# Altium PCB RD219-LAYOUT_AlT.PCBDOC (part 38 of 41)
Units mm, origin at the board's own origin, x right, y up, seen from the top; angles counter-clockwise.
Board outline 209.75 x 159.97 mm, 2 copper layers (TOP, BOTTOM), stack 0 mm thick; 398 components, 199 nets, 1469 pads, 0 vias.
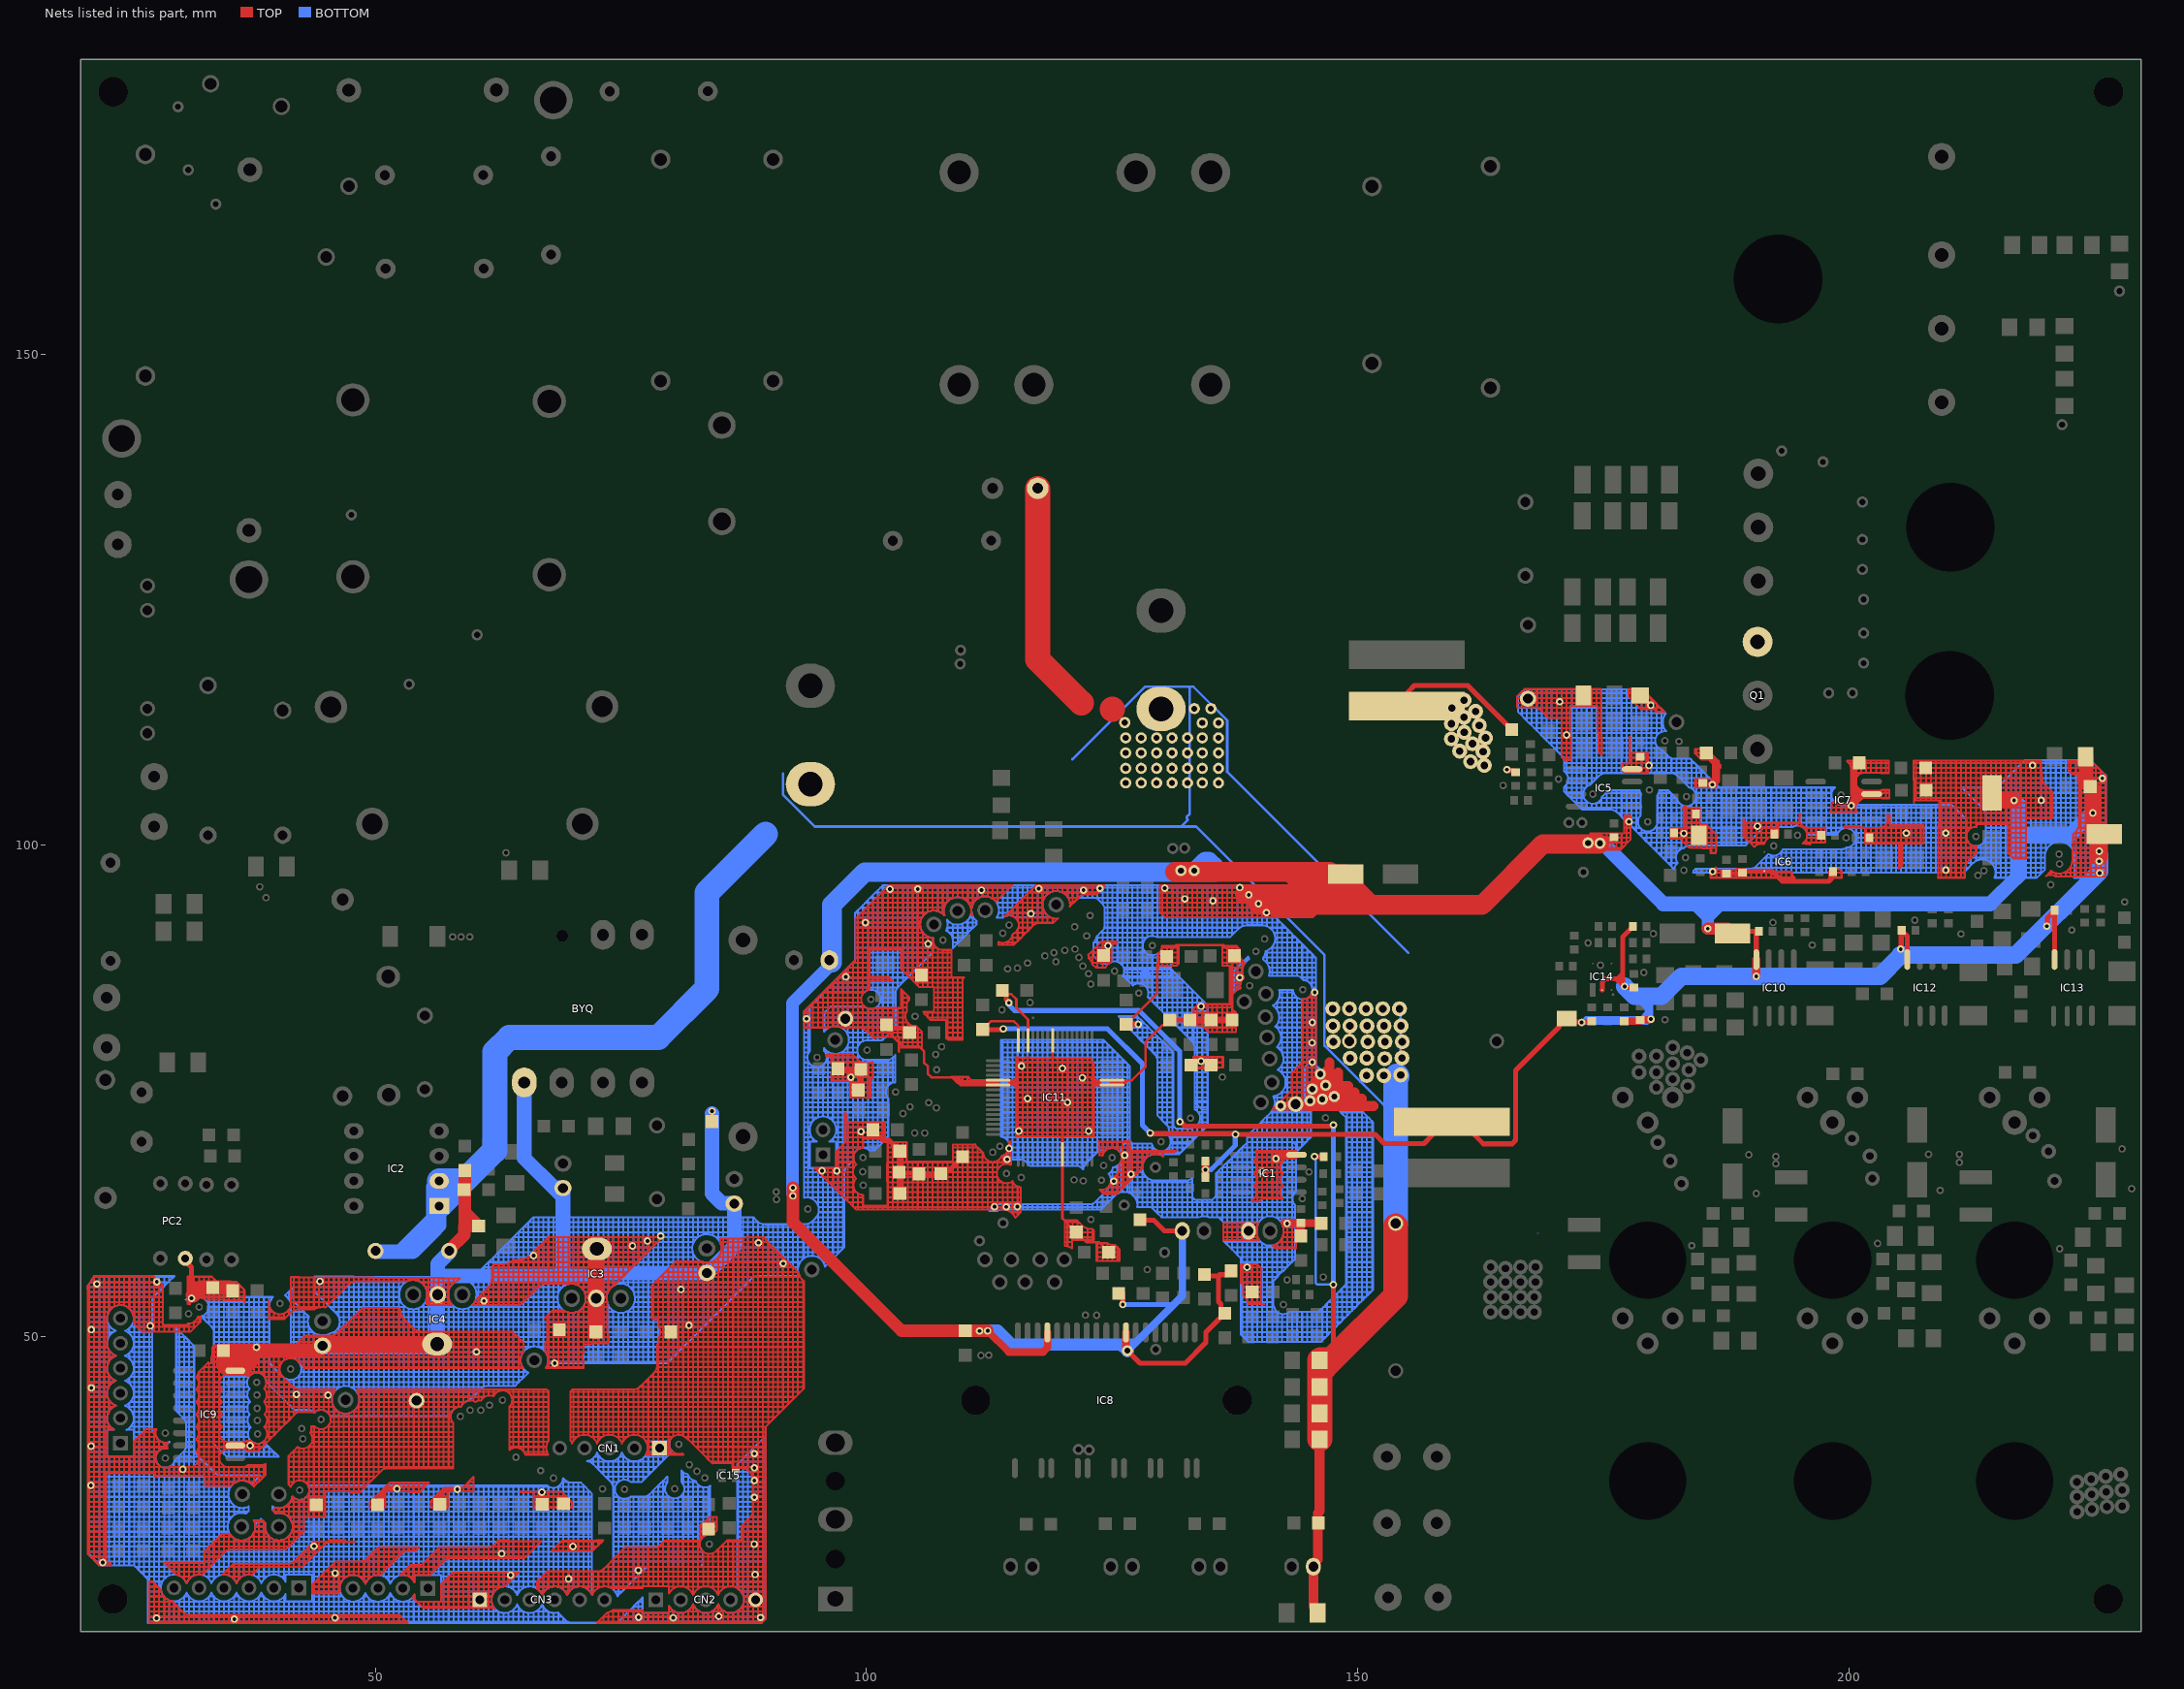
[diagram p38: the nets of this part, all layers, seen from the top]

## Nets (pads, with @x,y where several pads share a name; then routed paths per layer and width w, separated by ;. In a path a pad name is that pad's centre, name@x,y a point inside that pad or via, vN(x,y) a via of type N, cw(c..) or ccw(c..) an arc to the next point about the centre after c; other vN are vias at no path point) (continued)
GND: (continued)
  BOTTOM w0.203: 210.373,102.296 210.881,102.296 ; 210.373,102.804 210.373,103.312 ; 210.373,102.804 210.881,102.804 ; 210.373,103.312 210.373,103.82 ; 210.373,103.312 210.881,103.312 ; 210.373,103.82 210.373,104.107 ; 210.373,103.82 210.761,103.82 ; 210.373,104.107 210.474,104.107 210.761,103.82 ; 210.761,103.82 210.881,103.7 ; 210.881,97.212 210.881,97.216 ; 210.881,97.212 211.389,97.212 ; 210.881,97.216 210.881,97.724 ; 210.881,97.216 211.389,97.216 ; 210.881,97.724 210.881,98.232 ; 210.881,97.724 211.389,97.724 ; 210.881,98.232 210.881,98.74 ; 210.881,98.232 211.389,98.232 ; 210.881,98.74 210.881,99.248 ; 210.881,98.74 211.389,98.74 ; 210.881,99.248 210.881,99.756 ; 210.881,99.248 211.389,99.248 ; 210.881,99.756 210.881,100.264 ; 210.881,99.756 211.389,99.756 ; 210.881,100.264 210.881,100.772 ; 210.881,100.264 211.389,100.264 ; 210.881,100.772 210.881,101.28 ; 210.881,100.772 211.389,100.772 ; 210.881,101.28 210.881,101.788 ; 210.881,101.28 211.389,101.28 ; 210.881,101.788 210.881,102.296 ; 210.881,101.788 211.389,101.788 ; 210.881,102.296 210.881,102.804 ; 210.881,102.296 211.389,102.296 ; 210.881,102.804 210.881,103.312 ; 210.881,102.804 211.389,102.804 ; 210.881,103.312 210.881,103.7 ; 210.881,103.312 211.269,103.312 ; 210.881,103.7 211.269,103.312 ; 211.269,103.312 211.389,103.192 ; 211.389,97.212 211.389,97.216 ; 211.389,97.212 211.632,97.212 211.637,97.216 ; 211.389,97.216 211.389,97.724 ; 211.389,97.216 211.637,97.216 ; 211.389,97.724 211.897,97.724 ; 211.389,97.724 211.389,98.232 ; 211.389,98.232 211.897,98.232 ; 211.389,98.232 211.389,98.74 ; 211.389,98.74 211.897,98.74 ; 211.389,98.74 211.389,99.248 ; 211.389,99.248 211.389,99.756 ; 211.389,99.248 211.897,99.248 ; 211.389,99.756 211.897,99.756 ; 211.389,99.756 211.389,100.264 ; 211.389,100.264 211.389,100.772 ; 211.389,100.264 211.897,100.264 ; 211.389,100.772 211.897,100.772 ; 211.389,100.772 211.389,101.28 ; 211.389,101.28 211.389,101.788 ; 211.389,101.28 211.897,101.28 ; 211.389,101.788 211.389,102.296 ; 211.389,101.788 211.897,101.788 ; 211.389,102.296 211.897,102.296 ; 211.389,102.296 211.389,102.804 ; 211.389,102.804 211.389,103.192 ; 211.389,102.804 211.777,102.804 ; 211.389,103.192 211.777,102.804 ; 211.501,105.852 cw(c210.881,105.09) 211.576,105.785 ccw(c210.881,105.09) 211.501,105.852 ; 211.501,105.852 ccw(c210.881,105.09) 211.459,105.885 cw(c210.881,105.09) 211.501,105.852 ; 211.501,105.852 211.897,105.852 ; 211.637,97.216 211.897,97.476 ; 211.777,102.804 211.897,102.684 ; 211.897,97.476 212.145,97.724 ; 211.897,97.476 211.897,97.724 ; 211.897,97.724 211.897,98.232 ; 211.897,97.724 212.145,97.724 ; 211.897,98.232 211.897,98.74 ; 211.897,98.232 212.405,98.232 ; 211.897,98.74 211.897,99.248 ; 211.897,98.74 212.405,98.74 ; 211.897,99.248 211.897,99.756 ; 211.897,99.248 212.405,99.248 ; 211.897,99.756 212.405,99.756 ; 211.897,99.756 211.897,100.264 ; 211.897,100.264 211.897,100.772 ; 211.897,100.264 212.168,100.264 ; 211.897,100.772 211.897,101.28 ; 211.897,100.772 211.939,100.772 ; 211.897,101.28 211.897,101.788 ; 211.897,101.28 211.93,101.28 ; 211.897,101.788 211.897,102.296 ; 211.897,101.788 211.93,101.788 ; 211.897,102.296 211.93,102.296 ; 211.897,102.296 211.897,102.684 ; 211.897,102.684 211.93,102.651 211.93,102.296 ; 211.897,105.464 212.017,105.344 ; 211.897,105.464 211.897,105.852 ; 211.897,105.852 211.897,105.886 ; 211.897,105.852 212.405,105.852 ; 211.897,105.886 212.405,105.886 ; 211.93,100.905 ccw(c212.913,100.905) 211.939,100.772 ; 211.93,100.905 ccw(c212.913,100.905) 211.939,100.772 ; 211.93,100.905 211.93,101.28 ; 211.93,101.28 211.93,101.788 ; 211.93,101.788 211.93,102.296 ; 211.939,100.772 ccw(c212.913,100.905) 212.168,100.264 ; 211.939,100.772 ccw(c212.913,100.905) 212.168,100.264 ; 212.017,105.344 212.405,104.956 ; 212.017,105.344 212.405,105.344 ; 212.145,97.724 212.405,97.984 ; 212.168,100.264 ccw(c212.913,100.905) 212.171,100.26 ; 212.168,100.264 ccw(c212.913,100.905) 212.171,100.26 ; 212.171,100.26 ccw(c212.913,100.905) 212.405,100.064 ; 212.171,100.26 ccw(c212.913,100.905) 212.405,100.064 ; 212.405,97.984 212.592,98.172 cw(c213.548,97.216) 212.657,98.232 ; 212.405,97.984 212.405,98.232 ; 212.405,98.232 212.405,98.74 ; 212.405,98.232 212.657,98.232 ; 212.405,98.74 212.405,99.248 ; 212.405,98.74 212.913,98.74 ; 212.405,99.248 212.405,99.756 ; 212.405,99.248 212.913,99.248 ; 212.405,99.756 212.913,99.756 ; 212.405,99.756 212.405,100.064 ; 212.405,100.064 ccw(c212.913,100.905) 212.407,100.063 ; 212.405,100.064 ccw(c212.913,100.905) 212.407,100.063 ; 212.405,104.956 212.525,104.836 ; 212.405,104.956 212.405,105.344 ; 212.405,105.344 212.405,105.852 ; 212.405,105.344 212.913,105.344 ; 212.405,105.852 212.405,105.886 ; 212.405,105.852 212.913,105.852 ; 212.405,105.886 212.913,105.886 ; 212.407,100.063 ccw(c212.913,100.905) 212.913,99.923 ; 212.407,100.063 ccw(c212.913,100.905) 212.913,99.923 ; 212.525,104.836 212.913,104.448 ; 212.525,104.836 212.913,104.836 ; 212.657,98.232 cw(c213.548,97.216) 212.913,98.409 ; 212.913,98.409 cw(c213.548,97.216) 213.421,98.562 ; 212.913,98.409 212.913,98.74 ; 212.913,98.74 212.913,99.248 ; 212.913,98.74 213.421,98.74 ; 212.913,99.248 212.913,99.756 ; 212.913,99.248 213.421,99.248 ; 212.913,99.756 213.421,99.756 ; 212.913,99.756 212.913,99.923 ; 212.913,99.923 ccw(c212.913,100.905) 213.419,100.063 ; 212.913,99.923 ccw(c212.913,100.905) 213.419,100.063 ; 212.913,104.448 213.033,104.328 ; 212.913,104.448 212.913,104.836 ; 212.913,104.836 212.913,105.344 ; 212.913,104.836 213.421,104.836 ; 212.913,105.344 212.913,105.852 ; 212.913,105.344 213.421,105.344 ; 212.913,105.852 213.421,105.852 ; 212.913,105.852 212.913,105.886 ; 212.913,105.886 213.421,105.886 ; 213.033,104.328 213.421,104.328 ; 213.419,100.063 ccw(c212.913,100.905) 213.421,100.064 ; 213.419,100.063 ccw(c212.913,100.905) 213.421,100.064 ; 213.421,98.562 cw(c213.548,97.216) 213.921,98.515 cw(c213.548,97.216) 213.929,98.513 ; 213.421,98.562 213.421,98.74 ; 213.421,98.74 213.421,99.248 ; 213.421,98.74 213.929,98.74 ; 213.421,99.248 213.421,99.756 ; 213.421,99.248 213.929,99.248 ; 213.421,99.756 213.929,99.756 ; 213.421,99.756 213.421,100.064 ; 213.421,100.064 ccw(c212.913,100.905) 213.654,100.26 ; 213.421,100.064 ccw(c212.913,100.905) 213.654,100.26 ; 213.421,104.328 213.421,104.836 ; 213.421,104.328 213.929,104.328 ; 213.421,104.836 213.421,105.344 ; 213.421,104.836 213.929,104.836 ; 213.421,105.344 213.421,105.852 ; 213.421,105.344 213.929,105.344 ; 213.421,105.852 213.929,105.852 ; 213.421,105.852 213.421,105.886 ; 213.421,105.886 213.929,105.886 ; 213.654,100.26 ccw(c212.913,100.905) 213.657,100.264 ; 213.654,100.26 ccw(c212.913,100.905) 213.657,100.264 ; 213.657,100.264 ccw(c212.913,100.905) 213.886,100.772 ; 213.657,100.264 ccw(c212.913,100.905) 213.886,100.772 ; 213.657,100.264 213.929,100.264 ; 213.862,103.312 ccw(c212.913,103.058) 213.608,103.753 cw(c212.913,103.058) 213.862,103.312 ; 213.862,103.312 cw(c212.913,103.058) 213.895,103.058 ; 213.862,103.312 cw(c212.913,103.058) 213.895,103.058 ; 213.862,103.312 213.929,103.312 ; 213.886,100.772 ccw(c212.913,100.905) 213.895,100.905 ; 213.886,100.772 ccw(c212.913,100.905) 213.895,100.905 ; 213.886,100.772 213.929,100.772 ; 213.895,100.905 213.895,101.28 ; 213.895,101.28 213.929,101.28 ; 213.895,101.28 213.895,101.788 ; 213.895,101.788 213.929,101.788 ; 213.895,101.788 213.895,102.296 ; 213.895,102.296 213.929,102.296 ; 213.895,102.296 213.895,102.804 ; 213.895,102.804 213.929,102.804 ; 213.895,102.804 213.895,103.058 ; 213.929,98.513 cw(c213.548,97.216) 214.435,98.236 cw(c213.548,97.216) 214.437,98.234 ; 213.929,98.513 213.929,98.74 ; 213.929,98.74 213.929,99.248 ; 213.929,98.74 214.437,98.74 ; 213.929,99.248 213.929,99.756 ; 213.929,99.248 214.437,99.248 ; 213.929,99.756 213.929,100.264 ; 213.929,99.756 214.437,99.756 ; 213.929,100.264 213.929,100.772 ; 213.929,100.264 214.437,100.264 ; 213.929,100.772 214.437,100.772 ; 213.929,100.772 213.929,101.28 ; 213.929,101.28 213.929,101.788 ; 213.929,101.28 214.437,101.28 ; 213.929,101.788 213.929,102.296 ; 213.929,101.788 214.437,101.788 ; 213.929,102.296 213.929,102.804 ; 213.929,102.296 214.437,102.296 ; 213.929,102.804 213.929,103.312 ; 213.929,102.804 214.437,102.804 ; 213.929,103.312 213.929,103.82 ; 213.929,103.312 214.437,103.312 ; 213.929,103.82 213.929,104.328 ; 213.929,103.82 214.437,103.82 ; 213.929,104.328 213.929,104.836 ; 213.929,104.328 214.437,104.328 ; 213.929,104.836 213.929,105.344 ; 213.929,104.836 214.437,104.836 ; 213.929,105.344 213.929,105.852 ; 213.929,105.344 214.437,105.344 ; 213.929,105.852 213.929,105.886 ; 213.929,105.852 214.437,105.852 ; 213.929,105.886 214.437,105.886 ; 214.437,98.234 cw(c213.548,97.216) 214.439,98.232 ; 214.437,98.234 214.437,98.74 ; 214.437,98.74 214.945,98.74 ; 214.437,98.74 214.437,99.248 ; 214.437,99.248 214.437,99.756 ; 214.437,99.248 214.945,99.248 ; 214.437,99.756 214.945,99.756 ; 214.437,99.756 214.437,100.264 ; 214.437,100.264 214.437,100.772 ; 214.437,100.264 214.945,100.264 ; 214.437,100.772 214.945,100.772 ; 214.437,100.772 214.437,101.28 ; 214.437,101.28 214.437,101.788 ; 214.437,101.28 214.945,101.28 ; 214.437,101.788 214.437,102.296 ; 214.437,101.788 214.945,101.788 ; 214.437,102.296 214.437,102.804 ; 214.437,102.296 214.945,102.296 ; 214.437,102.804 214.437,103.312 ; 214.437,102.804 214.945,102.804 ; 214.437,103.312 214.437,103.82 ; 214.437,103.312 214.945,103.312 ; 214.437,103.82 214.945,103.82 ; 214.437,103.82 214.437,104.328 ; 214.437,104.328 214.437,104.836 ; 214.437,104.328 214.945,104.328 ; 214.437,104.836 214.437,105.344 ; 214.437,104.836 214.945,104.836 ; 214.437,105.344 214.437,105.852 ; 214.437,105.344 214.945,105.344 ; 214.437,105.852 214.945,105.852 ; 214.437,105.852 214.437,105.886 ; 214.437,105.886 214.731,105.886 ; 214.439,98.232 cw(c213.548,97.216) 214.801,97.724 ; 214.439,98.232 214.945,98.232 ; 214.731,105.886 ccw(c214.731,106.742) 214.945,105.913 ; 214.731,105.886 ccw(c214.731,106.742) 214.945,105.913 ; 214.801,97.724 cw(c213.548,97.216) 214.801,97.722 cw(c213.548,97.216) 214.9,97.216 ; 214.801,97.724 214.945,97.724 ; 214.9,97.216 214.945,97.216 ; 214.945,96.708 214.945,97.216 ; 214.945,96.708 215.453,96.708 ; 214.945,96.708 214.801,96.708 214.945,96.708 ; 214.945,96.708 215.453,96.708 ; 214.945,97.216 215.453,97.216 ; 214.945,97.216 214.945,97.724 ; 214.945,97.724 214.945,98.232 ; 214.945,97.724 215.453,97.724 ; 214.945,98.232 214.945,98.74 ; 214.945,98.232 215.453,98.232 ; 214.945,98.74 215.453,98.74 ; 214.945,98.74 214.945,99.248 ; 214.945,99.248 214.945,99.756 ; 214.945,99.248 215.453,99.248 ; 214.945,99.756 215.453,99.756 ; 214.945,99.756 214.945,100.264 ; 214.945,100.264 214.945,100.772 ; 214.945,100.264 215.453,100.264 ; 214.945,100.772 215.453,100.772 ; 214.945,100.772 214.945,101.28 ; 214.945,101.28 214.945,101.788 ; 214.945,101.28 215.453,101.28 ; 214.945,101.788 214.945,102.296 ; 214.945,101.788 215.453,101.788 ; 214.945,102.296 214.945,102.804 ; 214.945,102.296 215.453,102.296 ; 214.945,102.804 214.945,103.312 ; 214.945,102.804 215.453,102.804 ; 214.945,103.312 214.945,103.82 ; 214.945,103.312 215.453,103.312 ; 214.945,103.82 214.945,104.328 ; 214.945,103.82 215.453,103.82 ; 214.945,104.328 214.945,104.836 ; 214.945,104.328 215.453,104.328 ; 214.945,104.836 214.945,105.344 ; 214.945,104.836 215.453,104.836 ; 214.945,105.344 214.945,105.852 ; 214.945,105.344 215.453,105.344 ; 214.945,105.852 215.453,105.852 ; 214.945,105.852 214.945,105.913 ; 214.945,105.913 ccw(c214.731,106.742) 215.336,106.137 ; 214.945,105.913 ccw(c214.731,106.742) 215.336,106.137 ; 215.336,106.137 215.453,106.254 ; 215.453,96.708 215.453,97.216 ; 215.453,96.708 215.961,96.708 ; 215.453,96.708 215.961,96.708 ; 215.453,97.216 215.961,97.216 ; 215.453,97.216 215.453,97.724 ; 215.453,97.724 215.453,98.232 ; 215.453,97.724 215.961,97.724 ; 215.453,98.232 215.453,98.74 ; 215.453,98.232 215.961,98.232 ; 215.453,98.74 215.453,99.248 ; 215.453,98.74 215.961,98.74 ; 215.453,99.248 215.453,99.756 ; 215.453,99.248 215.961,99.248 ; 215.453,99.756 215.961,99.756 ; 215.453,99.756 215.453,100.264 ; 215.453,100.264 215.453,100.772 ; 215.453,100.264 215.961,100.264 ; 215.453,100.772 215.453,101.28 ; 215.453,100.772 215.961,100.772 ; 215.453,101.28 215.453,101.788 ; 215.453,101.28 215.961,101.28 ; 215.453,101.788 215.453,102.296 ; 215.453,101.788 215.961,101.788 ; 215.453,102.296 215.453,102.804 ; 215.453,102.296 215.961,102.296 ; 215.453,102.804 215.453,103.312 ; 215.453,102.804 215.961,102.804 ; 215.453,103.312 215.453,103.82 ; 215.453,103.312 215.961,103.312 ; 215.453,103.82 215.453,104.328 ; 215.453,103.82 215.961,103.82 ; 215.453,104.328 215.453,104.836 ; 215.453,104.328 215.961,104.328 ; 215.453,104.836 215.453,105.344 ; 215.453,104.836 215.961,104.836 ; 215.453,105.344 215.453,105.852 ; 215.453,105.344 215.961,105.344 ; 215.453,105.852 215.961,105.852 ; 215.453,105.852 215.453,106.254 ; 215.453,106.254 215.559,106.36 ; 215.559,106.36 215.961,106.762 ; 215.559,106.36 215.961,106.36 ; 215.961,96.708 215.961,97.216 ; 215.961,96.708 216.469,96.708 ; 215.961,96.708 216.469,96.708 ; 215.961,97.216 216.469,97.216 ; 215.961,97.216 215.961,97.724 ; 215.961,97.724 215.961,98.232 ; 215.961,97.724 216.469,97.724 ; 215.961,98.232 215.961,98.74 ; 215.961,98.232 216.469,98.232 ; 215.961,98.74 215.961,99.248 ; 215.961,98.74 216.469,98.74 ; 215.961,99.248 215.961,99.756 ; 215.961,99.248 216.469,99.248 ; 215.961,99.756 216.469,99.756 ; 215.961,99.756 215.961,100.264 ; 215.961,100.264 215.961,100.772 ; 215.961,100.264 216.469,100.264 ; 215.961,100.772 216.469,100.772 ; 215.961,100.772 215.961,101.28 ; 215.961,101.28 215.961,101.788 ; 215.961,101.28 216.469,101.28 ; 215.961,101.788 215.961,102.296 ; 215.961,101.788 216.469,101.788 ; 215.961,102.296 215.961,102.804 ; 215.961,102.296 216.469,102.296 ; 215.961,102.804 215.961,103.312 ; 215.961,102.804 216.469,102.804 ; 215.961,103.312 215.961,103.82 ; 215.961,103.312 216.469,103.312 ; 215.961,103.82 215.961,104.328 ; 215.961,103.82 216.469,103.82 ; 215.961,104.328 215.961,104.836 ; 215.961,104.328 216.469,104.328 ; 215.961,104.836 215.961,105.344 ; 215.961,104.836 216.469,104.836 ; 215.961,105.344 215.961,105.852 ; 215.961,105.344 216.469,105.344 ; 215.961,105.852 216.469,105.852 ; 215.961,105.852 215.961,106.36 ; 215.961,106.36 216.469,106.36 ; 215.961,106.36 215.961,106.762 ; 215.961,106.762 216.067,106.868 ; 216.067,106.868 216.469,107.27 ; 216.067,106.868 216.469,106.868 ; 216.469,96.708 216.469,97.216 ; 216.469,96.708 216.977,96.708 ; 216.469,96.708 216.977,96.708 ; 216.469,97.216 216.977,97.216 ; 216.469,97.216 216.469,97.724 ; 216.469,97.724 216.469,98.232 ; 216.469,97.724 216.977,97.724 ; 216.469,98.232 216.469,98.74 ; 216.469,98.232 216.977,98.232 ; 216.469,98.74 216.977,98.74 ; 216.469,98.74 216.469,99.248 ; 216.469,99.248 216.469,99.756 ; 216.469,99.248 216.977,99.248 ; 216.469,99.756 216.977,99.756 ; 216.469,99.756 216.469,100.264 ; 216.469,100.264 216.469,100.772 ; 216.469,100.264 216.977,100.264 ; 216.469,100.772 216.977,100.772 ; 216.469,100.772 216.469,101.28 ; 216.469,101.28 216.469,101.788 ; 216.469,101.28 216.977,101.28 ; 216.469,101.788 216.469,102.296 ; 216.469,101.788 216.977,101.788 ; 216.469,102.296 216.469,102.804 ; 216.469,102.296 216.977,102.296 ; 216.469,102.804 216.469,103.312 ; 216.469,102.804 216.977,102.804 ; 216.469,103.312 216.469,103.82 ; 216.469,103.312 216.977,103.312 ; 216.469,103.82 216.977,103.82 ; 216.469,103.82 216.469,104.328 ; 216.469,104.328 pad.@216.977,104.328 ; 216.469,104.328 216.469,104.836 ; 216.469,104.836 216.469,105.344 ; 216.469,104.836 pad.@216.977,104.836 ; 216.469,105.344 216.469,105.852 ; 216.469,105.344 216.977,105.344 ; 216.469,105.852 216.977,105.852 ; 216.469,105.852 216.469,106.36 ; 216.469,106.36 216.977,106.36 ; 216.469,106.36 216.469,106.868 ; 216.469,106.868 216.977,106.868 ; 216.469,106.868 216.469,107.27 ; 216.469,107.27 216.575,107.376 ; 216.575,107.376 216.977,107.778 ; 216.575,107.376 216.977,107.376 ; 216.977,96.708 216.977,97.216 ; 216.977,96.708 217.044,96.708 ; 216.977,96.708 217.044,96.708 ; 216.977,97.216 217.295,97.216 217.485,97.216 ; 216.977,97.216 216.977,97.724 ; 216.977,97.724 216.977,98.232 ; 216.977,97.724 217.295,97.724 217.485,97.724 ; 216.977,98.232 216.977,98.74 ; 216.977,98.232 217.295,98.232 217.485,98.232 ; 216.977,98.74 216.977,99.248 ; 216.977,98.74 217.295,98.74 217.485,98.74 ; 216.977,99.248 216.977,99.756 ; 216.977,99.248 217.295,99.248 217.485,99.248 ; 216.977,99.756 217.295,99.756 217.485,99.756 ; 216.977,99.756 216.977,100.264 ; 216.977,100.264 216.977,100.772 ; 216.977,100.264 217.295,100.264 217.485,100.264 ; 216.977,100.772 217.295,100.772 217.485,100.772 ; 216.977,100.772 216.977,101.28 ; 216.977,101.28 216.977,101.788 ; 216.977,101.28 217.295,101.28 217.485,101.28 ; 216.977,101.788 216.977,102.296 ; 216.977,101.788 217.295,101.788 217.485,101.788 ; 216.977,102.296 216.977,102.804 ; 216.977,102.296 217.295,102.296 217.485,102.296 ; 216.977,102.804 216.977,103.312 ; 216.977,102.804 217.295,102.804 217.485,102.804 ; 216.977,103.312 216.977,103.82 ; 216.977,103.312 217.295,103.312 217.485,103.312 ; 216.977,103.82 217.295,103.82 217.485,103.82 ; 216.977,103.82 pad.@216.977,104.328 ; pad.@216.977,104.328 216.977,104.455 pad.@216.977,104.836 ; pad.@216.977,104.328 217.104,104.328 217.485,104.328 ; pad.@216.977,104.836 216.977,105.344 ; pad.@216.977,104.836 217.485,104.836 ; 216.977,105.344 216.977,105.852 ; 216.977,105.344 217.485,105.344 ; 216.977,105.852 217.485,105.852 ; 216.977,105.852 216.977,106.36 ; 216.977,106.36 217.485,106.36 ; 216.977,106.36 216.977,106.868 ; 216.977,106.868 217.485,106.868 ; 216.977,106.868 216.977,107.376 ; 216.977,107.376 216.977,107.778 ; 216.977,107.376 217.485,107.376 ; 216.977,107.778 217.083,107.884 ; 217.044,96.708 217.485,96.708 ; 217.044,96.708 217.485,96.708 ; 217.083,107.884 217.485,107.884 ; 217.083,107.884 217.591,108.392 ; 217.485,96.708 217.485,97.216 ; 217.485,96.708 217.993,96.708 ; 217.485,96.708 217.993,96.708 ; 217.485,97.216 217.993,97.216 ; 217.485,97.216 217.485,97.724 ; 217.485,97.724 217.485,98.232 ; 217.485,97.724 217.993,97.724 ; 217.485,98.232 217.485,98.74 ; 217.485,98.232 217.993,98.232 ; 217.485,98.74 217.485,99.248 ; 217.485,98.74 217.993,98.74 ; 217.485,99.248 217.485,99.756 ; 217.485,99.248 217.993,99.248 ; 217.485,99.756 217.993,99.756 ; 217.485,99.756 217.485,100.264 ; 217.485,100.264 217.485,100.772 ; 217.485,100.264 217.993,100.264 ; 217.485,100.772 217.485,101.153 217.485,101.28 ; 217.485,100.772 217.993,100.772 ; 217.485,101.28 217.485,101.788 ; 217.485,101.28 217.993,101.28 ; 217.485,101.788 217.485,102.296 ; 217.485,101.788 217.993,101.788 ; 217.485,102.296 217.485,102.804 ; 217.485,102.296 217.993,102.296 ; 217.485,102.804 217.485,103.312 ; 217.485,102.804 217.993,102.804 ; 217.485,103.312 217.485,103.82 ; 217.485,103.312 217.993,103.312 ; 217.485,103.82 217.993,103.82 ; 217.485,103.82 217.485,104.328 ; 217.485,104.328 217.485,104.836 ; 217.485,104.328 217.993,104.328 ; 217.485,104.836 217.485,105.344 ; 217.485,104.836 217.993,104.836 ; 217.485,105.344 217.485,105.852 ; 217.485,105.344 217.993,105.344 ; 217.485,105.852 217.993,105.852 ; 217.485,105.852 217.485,106.36 ; 217.485,106.36 217.993,106.36 ; 217.485,106.36 217.485,106.868 ; 217.485,106.868 217.993,106.868 ; 217.485,106.868 217.485,107.376 ; 217.485,107.376 217.485,107.884 ; 217.485,107.376 217.993,107.376 ; 217.485,107.884 217.993,107.884 ; 217.591,108.392 217.993,108.392 ; 217.591,108.392 217.845,108.646 217.993,108.646 ; 217.993,96.708 217.993,97.216 ; 217.993,96.708 218.501,96.708 ; 217.993,96.708 218.501,96.708 ; 217.993,97.216 218.501,97.216 ; 217.993,97.216 217.993,97.724 ; 217.993,97.724 217.993,98.232 ; 217.993,97.724 218.501,97.724 ; 217.993,98.232 217.993,98.74 ; 217.993,98.232 218.501,98.232 ; 217.993,98.74 217.993,99.248 ; 217.993,98.74 218.501,98.74 ; 217.993,99.248 217.993,99.756 ; 217.993,99.248 218.501,99.248 ; 217.993,99.756 218.501,99.756 ; 217.993,99.756 217.993,100.264 ; 217.993,100.264 217.993,100.772 ; 217.993,100.264 218.501,100.264 ; 217.993,100.772 218.501,100.772 ; 217.993,100.772 217.993,101.153 217.993,101.28 ; 217.993,101.28 217.993,101.788 ; 217.993,101.28 218.501,101.28 ; 217.993,101.788 217.993,102.296 ; 217.993,101.788 218.501,101.788 ; 217.993,102.296 217.993,102.804 ; 217.993,102.296 218.501,102.296 ; 217.993,102.804 217.993,103.312 ; 217.993,102.804 218.501,102.804 ; 217.993,103.312 217.993,103.82 ; 217.993,103.312 218.501,103.312 ; 217.993,103.82 218.501,103.82 ; 217.993,103.82 217.993,104.328 ; 217.993,104.328 217.993,104.836 ; 217.993,104.328 218.501,104.328 ; 217.993,104.836 217.993,105.344 ; 217.993,104.836 218.501,104.836 ; 217.993,105.344 217.993,105.852 ; 217.993,105.344 218.501,105.344 ; 217.993,105.852 218.501,105.852 ; 217.993,105.852 217.993,106.36 ; 217.993,106.36 218.501,106.36 ; 217.993,106.36 217.993,106.868 ; 217.993,106.868 218.501,106.868 ; 217.993,106.868 217.993,107.376 ; 217.993,107.376 217.993,107.884 ; 217.993,107.376 218.501,107.376 ; 217.993,107.884 pad.@218.501,107.884 ; 217.993,107.884 217.993,108.392 ; 217.993,108.392 pad.@218.501,108.392 ; 217.993,108.392 217.993,108.646 ; 217.993,108.646 218.501,108.646 ; 218.501,96.708 219.009,96.708 ; 218.501,96.708 219.009,96.708 ; 218.501,96.708 218.501,97.216 ; 218.501,97.216 219.009,97.216 ; 218.501,97.216 218.501,97.724 ; 218.501,97.724 218.501,98.232 ; 218.501,97.724 219.009,97.724 ; 218.501,98.232 218.501,98.74 ; 218.501,98.232 219.009,98.232 ; 218.501,98.74 219.009,98.74 ; 218.501,98.74 218.501,99.248 ; 218.501,99.248 218.501,99.756 ; 218.501,99.248 219.009,99.248 ; 218.501,99.756 219.009,99.756 ; 218.501,99.756 218.501,100.264 ; 218.501,100.264 218.501,100.772 ; 218.501,100.264 219.009,100.264 ; 218.501,100.772 218.501,101.153 218.501,101.28 ; 218.501,100.772 219.009,100.772 ; 218.501,101.28 218.501,101.788 ; 218.501,101.28 219.009,101.28 ; 218.501,101.788 218.501,102.296 ; 218.501,101.788 219.009,101.788 ; 218.501,102.296 218.501,102.804 ; 218.501,102.296 219.009,102.296 ; 218.501,102.804 218.501,103.312 ; 218.501,102.804 219.009,102.804 ; 218.501,103.312 218.501,103.82 ; 218.501,103.312 219.009,103.312 ; 218.501,103.82 219.009,103.82 ; 218.501,103.82 218.501,104.328 ; 218.501,104.328 218.501,104.836 ; 218.501,104.328 219.009,104.328 ; 218.501,104.836 218.501,105.344 ; 218.501,104.836 219.009,104.836 ; 218.501,105.344 218.501,105.852 ; 218.501,105.344 219.009,105.344 ; 218.501,105.852 219.009,105.852 ; 218.501,105.852 218.501,106.36 ; 218.501,106.36 219.009,106.36 ; 218.501,106.36 218.501,106.868 ; 218.501,106.868 219.009,106.868 ; 218.501,106.868 218.501,107.376 ; 218.501,107.376 pad.@218.501,107.884 ; 218.501,107.376 219.009,107.376 ; pad.@218.501,107.884 pad.@218.501,108.392 ; pad.@218.501,107.884 219.009,107.884 ; pad.@218.501,108.392 218.501,108.646 ; pad.@218.501,108.392 219.009,108.392 ; 218.501,108.646 219.009,108.646 ; 219.009,96.708 219.009,97.216 ; 219.009,96.708 219.107,96.708 ; 219.009,96.708 219.107,96.708 ; 219.009,97.216 219.517,97.216 ; 219.009,97.216 219.009,97.724 ; 219.009,97.724 219.009,98.232 ; 219.009,97.724 219.517,97.724 ; 219.009,98.232 219.009,98.74 ; 219.009,98.232 219.517,98.232 ; 219.009,98.74 219.009,99.248 ; 219.009,98.74 219.517,98.74 ; 219.009,99.248 219.009,99.756 ; 219.009,99.248 219.517,99.248 ; 219.009,99.756 219.517,99.756 ; 219.009,99.756 219.009,100.264 ; 219.009,100.264 219.009,100.772 ; 219.009,100.264 219.517,100.264 ; 219.009,100.772 219.009,101.153 219.009,101.28 ; 219.009,100.772 219.517,100.772 ; 219.009,101.28 219.009,101.788 ; 219.009,101.28 219.517,101.28 ; 219.009,101.788 219.009,102.296 ; 219.009,101.788 219.517,101.788 ; 219.009,102.296 219.009,102.804 ; 219.009,102.296 219.517,102.296 ; 219.009,102.804 219.009,103.312 ; 219.009,102.804 219.517,102.804 ; 219.009,103.312 219.009,103.82 ; 219.009,103.312 219.517,103.312 ; 219.009,103.82 219.009,104.328 ; 219.009,103.82 219.517,103.82 ; 219.009,104.328 219.009,104.836 ; 219.009,104.328 pad.@219.517,104.328 ; 219.009,104.836 219.009,105.344 ; 219.009,104.836 pad.@219.517,104.836 ; 219.009,105.344 219.009,105.852 ; 219.009,105.344 219.517,105.344 ; 219.009,105.852 219.517,105.852 ; 219.009,105.852 219.009,106.36 ; 219.009,106.36 219.517,106.36 ; 219.009,106.36 219.009,106.868 ; 219.009,106.868 219.517,106.868 ; 219.009,106.868 219.009,107.376 ; 219.009,107.376 219.009,107.884 ; 219.009,107.376 219.517,107.376 ; 219.009,107.884 219.517,107.884 ; 219.009,107.884 219.009,108.392 ; 219.009,108.392 219.009,108.646 ; 219.009,108.392 219.517,108.392 ; 219.009,108.646 219.517,108.646 ; 219.107,96.708 219.458,97.059 cw(c220.519,95.997) 219.517,97.115 ; 219.517,97.115 cw(c220.519,95.997) 219.547,97.141 ; 219.517,97.115 219.517,97.216 ; 219.517,97.216 219.517,97.724 ; 219.517,97.724 219.517,98.232 ; 219.517,97.724 219.92,97.724 ; 219.517,98.232 219.517,98.74 ; 219.517,98.232 219.92,98.232 ; 219.517,98.74 219.517,99.248 ; 219.517,98.74 219.92,98.74 ; 219.517,99.248 219.517,99.756 ; 219.517,99.248 219.97,99.248 ; 219.517,99.756 220.025,99.756 ; 219.517,99.756 219.517,100.264 ; 219.517,100.264 219.517,100.772 ; 219.517,100.264 220.025,100.264 ; 219.517,100.772 219.517,101.153 219.517,101.28 ; 219.517,100.772 220.025,100.772 ; 219.517,101.28 219.517,101.788 ; 219.517,101.28 220.025,101.28 ; 219.517,101.788 219.517,102.296 ; 219.517,101.788 220.025,101.788 ; 219.517,102.296 219.517,102.804 ; 219.517,102.296 220.025,102.296 ; 219.517,102.804 219.517,103.312 ; 219.517,102.804 220.025,102.804 ; 219.517,103.312 219.517,103.82 ; 219.517,103.312 220.025,103.312 ; 219.517,103.82 pad.@219.517,104.328 ; 219.517,103.82 220.025,103.82 ; pad.@219.517,104.328 220.025,104.328 ; pad.@219.517,104.328 pad.@219.517,104.836 ; pad.@219.517,104.836 219.517,105.344 ; pad.@219.517,104.836 220.025,104.836 ; 219.517,105.344 219.517,105.852 ; 219.517,105.344 220.025,105.344 ; 219.517,105.852 219.517,106.36 ; 219.517,105.852 220.025,105.852 ; 219.517,106.36 220.025,106.36 ; 219.517,106.36 219.517,106.868 ; 219.517,106.868 220.025,106.868 ; 219.517,106.868 219.517,107.376 ; 219.517,107.376 219.517,107.884 ; 219.517,107.376 220.025,107.376 ; 219.517,107.884 220.025,107.884 ; 219.517,107.884 219.517,108.392 ; 219.517,108.392 220.025,108.392 ; 219.517,108.392 219.517,108.646 ; 219.517,108.646 220.025,108.646 ; 219.547,97.141 219.92,97.515 219.92,97.724 ; 219.92,97.724 219.92,98.232 ; 219.92,98.232 219.92,98.74 ; 219.92,98.74 219.92,98.867 cw(c221.422,98.867) 219.97,99.248 ; 219.97,99.248 cw(c221.422,98.867) 220.025,99.418 ; 220.025,99.418 cw(c221.422,98.867) 220.03,99.43 cw(c221.422,98.867) 220.212,99.756 ; 220.025,99.418 220.025,99.756 ; 220.025,99.756 220.025,100.264 ; 220.025,99.756 220.212,99.756 ; 220.025,100.264 220.025,100.772 ; 220.025,100.264 220.533,100.264 ; 220.025,100.772 220.025,101.153 220.025,101.28 ; 220.025,100.772 220.533,100.772 ; 220.025,101.28 220.025,101.788 ; 220.025,101.28 220.533,101.28 ; 220.025,101.788 220.025,102.296 ; 220.025,101.788 220.533,101.788 ; 220.025,102.296 220.025,102.804 ; 220.025,102.296 220.533,102.296 ; 220.025,102.804 220.025,103.312 ; 220.025,102.804 220.533,102.804 ; 220.025,103.312 220.025,103.82 ; 220.025,103.312 220.533,103.312 ; 220.025,103.82 220.025,104.328 ; 220.025,103.82 220.533,103.82 ; 220.025,104.328 220.533,104.328 ; 220.025,104.328 220.025,104.836 ; 220.025,104.836 220.025,105.344 ; 220.025,104.836 220.533,104.836 ; 220.025,105.344 220.025,105.852 ; 220.025,105.344 220.533,105.344 ; 220.025,105.852 220.025,106.36 ; 220.025,105.852 220.533,105.852 ; 220.025,106.36 220.025,106.868 ; 220.025,106.36 220.533,106.36 ; 220.025,106.868 220.025,107.376 ; 220.025,106.868 220.533,106.868 ; 220.025,107.376 220.025,107.884 ; 220.025,107.376 220.533,107.376 ; 220.025,107.884 220.025,108.392 ; 220.025,107.884 220.533,107.884 ; 220.025,108.392 220.025,108.646 ; 220.025,108.392 220.533,108.392 ; 220.025,108.646 220.533,108.646 ; 220.212,99.756 cw(c221.422,98.867) 220.533,100.077 ; 220.533,100.077 cw(c221.422,98.867) 220.871,100.264 ; 220.533,100.077 220.533,100.264 ; 220.533,100.264 220.533,100.772 ; 220.533,100.264 220.871,100.264 ; 220.533,100.772 220.533,101.153 220.533,101.28 ; 220.533,100.772 221.041,100.772 ; 220.533,101.28 220.533,101.788 ; 220.533,101.28 221.041,101.28 ; 220.533,101.788 220.533,102.296 ; 220.533,101.788 221.041,101.788 ; 220.533,102.296 220.533,102.804 ; 220.533,102.296 221.041,102.296 ; 220.533,102.804 220.533,103.312 ; 220.533,102.804 221.041,102.804 ; 220.533,103.312 220.533,103.82 ; 220.533,103.312 221.041,103.312 ; 220.533,103.82 220.533,104.328 ; 220.533,103.82 221.041,103.82 ; 220.533,104.328 220.533,104.836 ; 220.533,104.328 221.041,104.328 ; 220.533,104.836 220.533,105.344 ; 220.533,104.836 221.041,104.836 ; 220.533,105.344 220.533,105.852 ; 220.533,105.344 221.041,105.344 ; 220.533,105.852 220.533,106.36 ; 220.533,105.852 221.041,105.852 ; 220.533,106.36 220.533,106.868 ; 220.533,106.36 221.041,106.36 ; 220.533,106.868 220.533,107.376 ; 220.533,106.868 221.041,106.868 ; 220.533,107.376 220.533,107.884 ; 220.533,107.376 221.041,107.376 ; 220.533,107.884 220.533,108.392 ; 220.533,107.884 221.041,107.884 ; 220.533,108.392 220.533,108.646 ; 220.533,108.392 221.041,108.392 ; 220.533,108.646 221.041,108.646 ; 220.871,100.264 cw(c221.422,98.867) 221.033,100.317 cw(c221.422,98.867) 221.041,100.319 ; 221.041,100.319 cw(c221.422,98.867) 221.422,100.369 cw(c221.422,98.867) 221.549,100.363 ; 221.041,100.319 221.041,100.772 ; 221.041,100.772 221.041,101.153 221.041,101.28 ; 221.041,100.772 221.549,100.772 ; 221.041,101.28 221.041,101.788 ; 221.041,101.28 221.549,101.28 ; 221.041,101.788 221.041,102.296 ; 221.041,101.788 221.549,101.788 ; 221.041,102.296 221.041,102.804 ; 221.041,102.296 221.549,102.296 ; 221.041,102.804 221.041,103.312 ; 221.041,102.804 221.549,102.804 ; 221.041,103.312 221.041,103.82 ; 221.041,103.312 221.549,103.312 ; 221.041,103.82 221.041,104.328 ; 221.041,103.82 221.549,103.82 ; 221.041,104.328 221.041,104.836 ; 221.041,104.328 221.549,104.328 ; 221.041,104.836 221.041,105.344 ; 221.041,104.836 221.549,104.836 ; 221.041,105.344 221.041,105.852 ; 221.041,105.344 221.549,105.344 ; 221.041,105.852 221.041,106.36 ; 221.041,105.852 221.549,105.852 ; 221.041,106.36 221.041,106.868 ; 221.041,106.36 221.549,106.36 ; 221.041,106.868 221.041,107.376 ; 221.041,106.868 221.549,106.868 ; 221.041,107.376 221.041,107.884 ; 221.041,107.376 221.549,107.376 ; 221.041,107.884 221.041,108.392 ; 221.041,107.884 221.549,107.884 ; 221.041,108.392 221.041,108.646 ; 221.041,108.392 221.549,108.392 ; 221.041,108.646 221.549,108.646 ; 221.549,100.363 cw(c221.422,98.867) 221.553,100.363 cw(c221.422,98.867) 221.973,100.264 ; 221.549,100.363 221.549,100.772 ; 221.549,100.772 221.549,101.153 221.549,101.28 ; 221.549,100.772 222.057,100.772 ; 221.549,101.28 221.549,101.788 ; 221.549,101.28 222.057,101.28 ; 221.549,101.788 221.549,102.296 ; 221.549,101.788 222.057,101.788 ; 221.549,102.296 221.549,102.804 ; 221.549,102.296 222.057,102.296 ; 221.549,102.804 221.549,103.312 ; 221.549,102.804 222.057,102.804 ; 221.549,103.312 221.549,103.82 ; 221.549,103.312 222.057,103.312 ; 221.549,103.82 221.549,104.328 ; 221.549,103.82 222.057,103.82 ; 221.549,104.328 221.549,104.836 ; 221.549,104.328 222.057,104.328 ; 221.549,104.836 221.549,105.344 ; 221.549,104.836 222.057,104.836 ; 221.549,105.344 221.549,105.852 ; 221.549,105.344 222.057,105.344 ; 221.549,105.852 221.549,106.36 ; 221.549,105.852 222.057,105.852 ; 221.549,106.36 221.549,106.868 ; 221.549,106.36 222.057,106.36 ; 221.549,106.868 221.549,107.376 ; 221.549,106.868 222.057,106.868 ; 221.549,107.376 221.549,107.884 ; 221.549,107.376 222.057,107.376 ; 221.549,107.884 221.549,108.392 ; 221.549,107.884 222.057,107.884 ; 221.549,108.392 221.549,108.646 ; 221.549,108.392 222.057,108.392 ; 221.549,108.646 222.057,108.646 ; 221.973,100.264 222.057,100.264 ; 222.057,100.264 222.057,100.772 ; 222.057,100.264 222.565,100.264 ; 222.057,100.264 222.057,100.228 cw(c221.422,98.867) 222.565,99.841 ; 222.057,100.772 222.565,100.772 ; 222.057,100.772 222.057,101.153 222.057,101.28 ; 222.057,101.28 222.057,101.788 ; 222.057,101.28 222.565,101.28 ; 222.057,101.788 222.057,102.296 ; 222.057,101.788 222.565,101.788 ; 222.057,102.296 222.057,102.804 ; 222.057,102.296 222.565,102.296 ; 222.057,102.804 222.057,103.312 ; 222.057,102.804 222.565,102.804 ; 222.057,103.312 222.057,103.82 ; 222.057,103.312 222.565,103.312 ; 222.057,103.82 222.565,103.82 ; 222.057,103.82 222.057,104.328 ; 222.057,104.328 222.057,104.836 ; 222.057,104.328 222.565,104.328 ; 222.057,104.836 222.057,105.344 ; 222.057,104.836 222.565,104.836 ; 222.057,105.344 222.057,105.852 ; 222.057,105.344 222.565,105.344 ; 222.057,105.852 222.565,105.852 ; 222.057,105.852 222.057,106.36 ; 222.057,106.36 222.565,106.36 ; 222.057,106.36 222.057,106.868 ; 222.057,106.868 222.565,106.868 ; 222.057,106.868 222.057,107.376 ; 222.057,107.376 222.057,107.884 ; 222.057,107.376 222.565,107.376 ; 222.057,107.884 222.565,107.884 ; 222.057,107.884 222.057,108.392 ; 222.057,108.392 222.565,108.392 ; 222.057,108.392 222.057,108.646 ; 222.057,108.646 222.565,108.646 ; 222.565,99.841 cw(c221.422,98.867) 222.632,99.756 ; 222.565,99.841 222.565,100.264 ; 222.565,100.264 222.565,100.772 ; 222.565,100.264 223.073,100.264 ; 222.565,100.772 223.073,100.772 ; 222.565,100.772 222.565,101.153 222.565,101.28 ; 222.565,101.28 222.692,101.28 223.073,101.28 ; 222.565,101.28 222.565,101.788 ; 222.565,101.788 222.565,102.296 ; 222.565,101.788 223.073,101.788 ; 222.565,102.296 222.565,102.804 ; 222.565,102.296 223.073,102.296 ; 222.565,102.804 222.565,103.312 ; 222.565,102.804 223.073,102.804 ; 222.565,103.312 222.565,103.82 ; 222.565,103.312 223.073,103.312 ; 222.565,103.82 222.565,104.328 ; 222.565,103.82 223.073,103.82 ; 222.565,104.328 222.565,104.836 ; 222.565,104.328 223.073,104.328 ; 222.565,104.836 222.565,105.344 ; 222.565,104.836 223.073,104.836 ; 222.565,105.344 222.565,105.852 ; 222.565,105.344 223.073,105.344 ; 222.565,105.852 222.565,106.36 ; 222.565,105.852 223.073,105.852 ; 222.565,106.36 222.565,106.868 ; 222.565,106.36 223.073,106.36 ; 222.565,106.868 222.565,107.376 ; 222.565,106.868 223.073,106.868 ; 222.565,107.376 222.565,107.884 ; 222.565,107.376 223.073,107.376 ; 222.565,107.884 222.565,108.392 ; 222.565,107.884 223.073,107.884 ; 222.565,108.392 222.565,108.646 ; 222.565,108.392 223.073,108.392 ; 222.565,108.646 223.073,108.646 ; 222.632,99.756 cw(c221.422,98.867) 222.874,99.248 ; 222.632,99.756 223.073,99.756 ; 222.874,99.248 cw(c221.422,98.867) 222.924,98.867 222.924,98.74 ; 222.874,99.248 223.073,99.248 ; 222.924,96.893 cw(c221.422,96.893) 222.912,96.71 ccw(c221.422,96.893) 222.924,96.893 ; 222.924,96.893 222.924,97.216 ; 222.924,97.216 223.073,97.216 ; 222.924,97.216 222.924,97.724 ; 222.924,97.724 222.924,98.232 ; 222.924,97.724 223.073,97.724 ; 222.924,98.232 222.924,98.74 ; 222.924,98.232 223.073,98.232 ; 222.924,98.74 223.073,98.74 ; 223.073,96.708 223.073,97.216 ; 223.073,96.708 223.581,96.708 ; 223.073,96.708 222.912,96.708 223.073,96.708 ; 223.073,96.708 223.581,96.708 ; 223.073,97.216 223.073,97.724 ; 223.073,97.216 223.581,97.216 ; 223.073,97.724 223.073,98.232 ; 223.073,97.724 223.581,97.724 ; 223.073,98.232 223.073,98.74 ; 223.073,98.232 223.581,98.232 ; 223.073,98.74 223.073,99.248 ; 223.073,98.74 223.581,98.74 ; 223.073,99.248 223.581,99.248 ; 223.073,99.248 223.073,99.756 ; 223.073,99.756 223.581,99.756 ; 223.073,99.756 223.073,100.264 ; 223.073,100.264 223.073,100.772 ; 223.073,100.264 223.581,100.264 ; 223.073,100.772 223.581,100.772 ; 223.073,100.772 223.073,101.28 ; 223.073,101.28 223.073,101.661 223.073,101.788 ; 223.073,101.28 223.581,101.28 ; 223.073,101.788 223.2,101.788 223.581,101.788 ; 223.073,101.788 223.073,102.296 ; 223.073,102.296 223.073,102.804 ; 223.073,102.296 223.581,102.296 ; 223.073,102.804 223.073,103.312 ; 223.073,102.804 223.581,102.804 ; 223.073,103.312 223.073,103.82 ; 223.073,103.312 223.581,103.312 ; 223.073,103.82 223.073,104.328 ; 223.073,103.82 223.581,103.82 ; 223.073,104.328 223.073,104.836 ; 223.073,104.328 223.581,104.328 ; 223.073,104.836 223.073,105.344 ; 223.073,104.836 223.581,104.836 ; 223.073,105.344 223.073,105.852 ; 223.073,105.344 223.581,105.344 ; 223.073,105.852 223.073,106.36 ; 223.073,105.852 223.581,105.852 ; 223.073,106.36 223.073,106.868 ; 223.073,106.36 223.581,106.36 ; 223.073,106.868 223.073,107.376 ; 223.073,106.868 223.581,106.868 ; 223.073,107.376 223.073,107.884 ; 223.073,107.376 223.581,107.376 ; 223.073,107.884 223.073,108.392 ; 223.073,107.884 223.581,107.884 ; 223.073,108.392 223.073,108.646 ; 223.073,108.392 223.581,108.392 ; 223.073,108.646 223.581,108.646 ; 223.581,96.708 223.581,97.216 ; 223.581,96.708 224.089,96.708 ; 223.581,96.708 224.089,96.708 ; 223.581,97.216 223.581,97.724 ; 223.581,97.216 224.089,97.216 ; 223.581,97.724 223.581,98.232 ; 223.581,97.724 224.089,97.724 ; 223.581,98.232 223.581,98.74 ; 223.581,98.232 224.089,98.232 ; 223.581,98.74 223.581,99.248 ; 223.581,98.74 224.089,98.74 ; 223.581,99.248 223.581,99.756 ; 223.581,99.248 224.089,99.248 ; 223.581,99.756 223.581,100.264 ; 223.581,99.756 224.089,99.756 ; 223.581,100.264 223.581,100.772 ; 223.581,100.264 224.089,100.264 ; 223.581,100.772 223.581,101.28 ; 223.581,100.772 224.089,100.772 ; 223.581,101.28 223.581,101.788 ; 223.581,101.28 224.089,101.28 ; 223.581,101.788 223.581,102.169 223.581,102.296 ; 223.581,101.788 224.089,101.788 ; 223.581,102.296 223.581,102.804 ; 223.581,102.296 223.708,102.296 224.089,102.296 ; 223.581,102.804 223.581,103.312 ; 223.581,102.804 224.089,102.804 ; 223.581,103.312 223.581,103.82 ; 223.581,103.312 224.089,103.312 ; 223.581,103.82 223.581,104.328 ; 223.581,103.82 224.089,103.82 ; 223.581,104.328 223.581,104.836 ; 223.581,104.328 224.089,104.328 ; 223.581,104.836 223.581,105.344 ; 223.581,104.836 224.089,104.836 ; 223.581,105.344 223.581,105.852 ; 223.581,105.344 224.089,105.344 ; 223.581,105.852 223.581,106.36 ; 223.581,105.852 224.089,105.852 ; 223.581,106.36 223.581,106.868 ; 223.581,106.36 224.089,106.36 ; 223.581,106.868 223.581,107.376 ; 223.581,106.868 224.089,106.868 ; 223.581,107.376 223.581,107.884 ; 223.581,107.376 224.089,107.376 ; 223.581,107.884 223.581,108.392 ; 223.581,107.884 224.089,107.884 ; 223.581,108.392 223.581,108.646 ; 223.581,108.392 224.089,108.392 ; 223.581,108.646 224.089,108.646 ; 224.089,96.708 224.089,97.216 ; 224.089,96.708 224.343,96.708 ; 224.089,96.708 224.343,96.708 ; 224.089,97.216 224.597,97.216 ; 224.089,97.216 224.089,97.724 ; 224.089,97.724 224.597,97.724 ; 224.089,97.724 224.089,98.232 ; 224.089,98.232 224.597,98.232 ; 224.089,98.232 224.089,98.74 ; 224.089,98.74 224.597,98.74 ; 224.089,98.74 224.089,99.248 ; 224.089,99.248 224.597,99.248 ; 224.089,99.248 224.089,99.756 ; 224.089,99.756 224.597,99.756 ; 224.089,99.756 224.089,100.264 ; 224.089,100.264 224.089,100.772 ; 224.089,100.264 224.597,100.264 ; 224.089,100.772 224.597,100.772 ; 224.089,100.772 224.089,101.28 ; 224.089,101.28 224.089,101.788 ; 224.089,101.28 224.597,101.28 ; 224.089,101.788 224.089,102.296 ; 224.089,101.788 224.597,101.788 ; 224.089,102.296 224.089,102.677 224.089,102.804 ; 224.089,102.296 224.597,102.296 ; 224.089,102.804 224.216,102.804 224.597,102.804 ; 224.089,102.804 224.089,103.312 ; 224.089,103.312 224.089,103.82 ; 224.089,103.312 pad.@224.597,103.312 ; 224.089,103.82 224.597,103.82 ; 224.089,103.82 224.089,104.328 ; 224.089,104.328 224.089,104.836 ; 224.089,104.328 224.597,104.328 ; 224.089,104.836 224.089,105.344 ; 224.089,104.836 224.597,104.836 ; 224.089,105.344 224.089,105.852 ; 224.089,105.344 224.597,105.344 ; 224.089,105.852 224.597,105.852 ; 224.089,105.852 224.089,106.36 ; 224.089,106.36 224.597,106.36 ; 224.089,106.36 224.089,106.868 ; 224.089,106.868 224.597,106.868 ; 224.089,106.868 224.089,107.376 ; 224.089,107.376 224.089,107.884 ; 224.089,107.376 224.597,107.376 ; 224.089,107.884 224.597,107.884 ; 224.089,107.884 224.089,108.392 ; 224.089,108.392 224.597,108.392 ; 224.089,108.392 224.089,108.646 ; 224.089,108.646 224.597,108.646 ; 224.343,96.708 224.851,97.216 ; 224.597,97.216 224.597,97.724 ; 224.597,97.216 224.851,97.216 ; 224.597,97.724 224.597,98.232 ; 224.597,97.724 225.105,97.724 ; 224.597,98.232 224.597,98.74 ; 224.597,98.232 225.105,98.232 ; 224.597,98.74 225.105,98.74 ; 224.597,98.74 224.597,99.248 ; 224.597,99.248 225.105,99.248 ; 224.597,99.248 224.597,99.756 ; 224.597,99.756 225.105,99.756 ; 224.597,99.756 224.597,100.264 ; 224.597,100.264 224.597,100.772 ; 224.597,100.264 225.105,100.264 ; 224.597,100.772 225.105,100.772 ; 224.597,100.772 224.597,101.28 ; 224.597,101.28 224.597,101.788 ; 224.597,101.28 225.105,101.28 ; 224.597,101.788 224.597,102.296 ; 224.597,101.788 225.105,101.788 ; 224.597,102.296 224.597,102.804 ; 224.597,102.296 225.105,102.296 ; 224.597,102.804 224.597,103.185 pad.@224.597,103.312 ; 224.597,102.804 225.105,102.804 ; pad.@224.597,103.312 224.597,103.82 ; pad.@224.597,103.312 224.724,103.312 pad.@225.105,103.312 ; 224.597,103.82 224.597,104.328 ; 224.597,103.82 225.105,103.82 ; 224.597,104.328 224.597,104.836 ; 224.597,104.328 225.105,104.328 ; 224.597,104.836 224.597,105.344 ; 224.597,104.836 225.105,104.836 ; 224.597,105.344 224.597,105.852 ; 224.597,105.344 225.105,105.344 ; 224.597,105.852 224.597,106.36 ; 224.597,105.852 225.105,105.852 ; 224.597,106.36 224.597,106.868 ; 224.597,106.36 225.105,106.36 ; 224.597,106.868 224.597,107.376 ; 224.597,106.868 225.105,106.868 ; 224.597,107.376 224.597,107.884 ; 224.597,107.376 225.105,107.376 ; 224.597,107.884 225.105,107.884 ; 224.597,107.884 224.597,108.392 ; 224.597,108.392 224.597,108.646 ; 224.597,108.646 225.613,107.63 ; 224.851,97.216 225.105,97.47 ; 225.105,97.47 225.359,97.724 ; 225.105,97.47 225.105,97.724 ; 225.105,97.724 225.105,98.232 ; 225.105,97.724 225.359,97.724 ; 225.105,98.232 225.486,98.232 pad.@225.613,98.232 ; 225.105,98.232 225.105,98.74 ; 225.105,98.74 225.105,99.248 ; 225.105,98.74 225.486,98.74 225.613,98.74 ; 225.105,99.248 pad.@225.613,99.248 ; 225.105,99.248 225.105,99.756 ; 225.105,99.756 225.105,100.264 ; 225.105,99.756 225.613,99.756 ; 225.105,100.264 225.105,100.772 ; 225.105,100.264 225.613,100.264 ; 225.105,100.772 225.613,100.772 ; 225.105,100.772 225.105,101.28 ; 225.105,101.28 225.105,101.788 ; 225.105,101.28 225.613,101.28 ; 225.105,101.788 225.105,102.296 ; 225.105,101.788 225.613,101.788 ; 225.105,102.296 225.105,102.804 ; 225.105,102.296 225.613,102.296 ; 225.105,102.804 225.613,102.804 ; 225.105,102.804 pad.@225.105,103.312 ; pad.@225.105,103.312 225.105,103.82 ; pad.@225.105,103.312 225.613,103.312 ; 225.105,103.82 225.105,104.328 ; 225.105,103.82 225.613,103.82 ; 225.105,104.328 225.105,104.836 ; 225.105,104.328 225.613,104.328 ; 225.105,104.836 225.105,105.344 ; 225.105,104.836 225.613,104.836 ; 225.105,105.344 225.105,105.852 ; 225.105,105.344 225.613,105.344 ; 225.105,105.852 225.105,106.36 ; 225.105,105.852 225.613,105.852 ; 225.105,106.36 225.105,106.868 ; 225.105,106.36 225.613,106.36 ; 225.105,106.868 225.105,107.376 ; 225.105,106.868 pad.@225.613,106.868 ; 225.105,107.376 225.105,107.884 ; 225.105,107.376 225.613,107.376 ; 225.359,97.724 225.486,97.851 225.743,98.108 225.867,98.232 ; pad.@225.613,98.232 225.867,98.232 ; pad.@225.613,98.232 225.613,98.74 ; 225.613,98.74 pad.@225.613,99.248 ; pad.@225.613,99.248 226.121,99.248 ; pad.@225.613,99.248 225.613,99.756 ; 225.613,99.756 226.121,99.756 ; 225.613,99.756 225.613,100.264 ; 225.613,100.264 225.613,100.772 ; 225.613,100.264 226.121,100.264 ; 225.613,100.772 226.121,100.772 ; 225.613,100.772 225.613,101.28 ; 225.613,101.28 226.121,101.28 ; 225.613,101.28 225.613,101.788 ; 225.613,101.788 226.121,101.788 ; 225.613,101.788 225.613,102.296 ; 225.613,102.296 225.613,102.804 ; 225.613,102.296 226.121,102.296 ; 225.613,102.804 225.613,103.312 ; 225.613,102.804 226.121,102.804 ; 225.613,103.312 225.613,103.82 ; 225.613,103.312 226.121,103.312 ; 225.613,103.82 225.613,104.328 ; 225.613,103.82 226.121,103.82 ; 225.613,104.328 225.613,104.836 ; 225.613,104.328 226.121,104.328 ; 225.613,104.836 225.613,105.344 ; 225.613,104.836 226.121,104.836 ; 225.613,105.344 225.613,105.852 ; 225.613,105.344 226.121,105.344 ; 225.613,105.852 226.121,105.852 ; 225.613,105.852 225.613,106.36 ; 225.613,106.36 226.121,106.36 ; 225.613,106.36 pad.@225.613,106.868 ; pad.@225.613,106.868 225.613,107.376 ; pad.@225.613,106.868 pad.@226.121,106.868 ; 225.613,107.376 225.613,107.63 ; 225.613,107.376 225.867,107.376 ; 225.613,107.63 225.867,107.376 ; 225.867,98.232 226.121,98.486 226.121,99.248 ; 225.867,107.376 226.099,107.144 226.121,107.122 ; 226.121,99.248 226.121,99.756 ; 226.121,99.756 226.121,100.264 ; 226.121,100.264 226.121,100.772 ; 226.121,100.264 226.121,100.772 ; 226.121,100.772 226.121,101.28 ; 226.121,100.772 226.121,101.28 ; 226.121,101.28 226.121,101.788 ; 226.121,101.28 226.121,101.788 ; 226.121,101.788 226.121,102.296 ; 226.121,101.788 226.121,102.296 ; 226.121,102.296 226.121,102.804 ; 226.121,102.296 226.121,102.804 ; 226.121,102.804 226.121,103.312 ; 226.121,102.804 226.121,103.312 ; 226.121,103.312 226.121,103.82 ; 226.121,103.312 226.121,104.328 ; 226.121,103.82 226.121,104.328 ; 226.121,104.328 226.121,104.836 ; 226.121,104.328 226.121,104.836 ; 226.121,104.836 226.121,105.344 ; 226.121,104.836 226.121,105.344 ; 226.121,105.344 226.121,105.852 ; 226.121,105.344 226.121,105.852 ; 226.121,105.852 226.121,106.36 ; 226.121,105.852 226.121,106.36 ; 226.121,106.36 pad.@226.121,106.868 ; 226.121,106.36 226.121,106.822 pad.@226.121,106.868 ; pad.@226.121,106.868 226.121,107.122 ; pad.@226.121,106.868 226.121,107.122 ; 40.808,54.227 ccw(c40.32,54.925) 40.922,54.323 cw(c40.32,54.925) 40.808,54.227 ; 133.284,79.841 cw(c132.522,79.453) 133.326,79.746 ccw(c132.522,79.453) 133.284,79.841
  BOTTOM w0.254: 91.49,107.291 91.49,105.175 94.75,101.915 132.014,101.915 ; EC2.2@94.295,106.233 EC2.2@94.545,106.233 ; 120.965,108.773 128.331,116.139 132.754,116.139 ; 126.831,69.865 127.038,69.657 ; 145.251,72.988 145.476,73.213 ; pad.@145.598,68.345 145.695,68.248 145.695,67.977 145.73,67.943 145.73,55.455 145.879,55.306 pad.@147.508,55.306 ; pad.@145.73,75.372 145.857,75.245 145.937,75.165 ; 152.687,73.535 150.269,75.954 146.619,79.603 146.619,88.834 133.538,101.915 132.014,101.915 ; pad.@153.871,76.4 153.982,76.511 154.239,76.769 154.354,76.883 pad.@154.354,83.172 ; 155.14,89.046 136.713,107.473 136.713,112.71 133.284,116.139 132.754,116.139 ; 132.014,101.915 132.713,102.614 132.596,102.73 132.596,102.931 132.723,103.058 132.754,103.058 132.903,103.207 132.903,107.837 132.903,115.99 132.754,116.139
  BOTTOM w0.508: pad.@113.925,81.327 124.535,81.327 128.077,77.785 128.077,71.54 128.877,70.74 pad.@128.877,70.723 ; pad.@114.487,83.976 114.536,83.928 114.536,83.706 115.047,83.195 116.984,83.195 127.747,83.195 131.887,79.055 131.887,71.892 pad.@131.897,71.882 ; pad.@126.078,53.283 126.087,53.274 131.252,53.274 ; pad.@134.499,66.997 134.514,67.012 135.084,67.012 137.527,69.455 137.527,70.568 pad.@137.557,70.597 ; pad.@147.508,55.306 147.508,71.534 pad.@147.522,71.548 ; pad.@172.789,81.977 pad.@172.858,81.977 ; 178.163,84.643 179.306,83.5 179.438,83.5 ; 185.481,94.051 185.624,93.908 ; pad.@172.858,81.977 179.438,81.977 ; pad.@172.858,81.977 173.238,82.357 178.877,82.357 ; 178.877,82.357 179.438,82.918 ; 178.877,82.357 179.311,82.357 179.438,82.484 ; 179.438,81.977 179.773,82.312 pad.@179.842,82.312 179.842,84.567 179.766,84.643 179.438,84.315 179.438,83.5 ; 179.438,81.977 179.438,82.484 ; 179.438,82.484 179.438,82.918 ; 179.438,82.918 179.438,83.5
  BOTTOM w0.762: 125.918,49.21 126.172,49.464 127.442,49.464 ; pad.@126.553,48.575 127.442,49.464 ; 128.204,86.929 128.52,86.929 ; EC7.2@132.141,60.767 132.141,54.163 131.252,53.274 127.442,49.464 ; EC16.2@138.73,59.953 138.731,59.954 138.731,60.132 138.731,60.626 138.745,60.64 EC16.2@138.872,60.767 EC16.2@138.872,60.917 ; pad.@141.546,68.133 pad.@141.666,68.133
